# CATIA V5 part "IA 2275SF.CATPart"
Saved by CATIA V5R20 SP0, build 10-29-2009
Part number: IA 2275SF
Revision: ANY
Definition: UNKNOWN
Nomenclature: IA 2275SF
Source: Unknown
Bounding box of the stored display mesh (mm): x -1.102 to 1.102, y -0.001 to 7.75, z -1.102 to 1.102
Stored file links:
  C:\Users\Utente\Desktop\IO LAVORO\3D X SITO CF\CUMSA\3D files FA\FA 0422SF\IA 2275SF.CATPart

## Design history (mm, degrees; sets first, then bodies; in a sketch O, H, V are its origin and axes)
Body1 "Cortar-Extruir2" (main body)
  Solid1: solid without history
